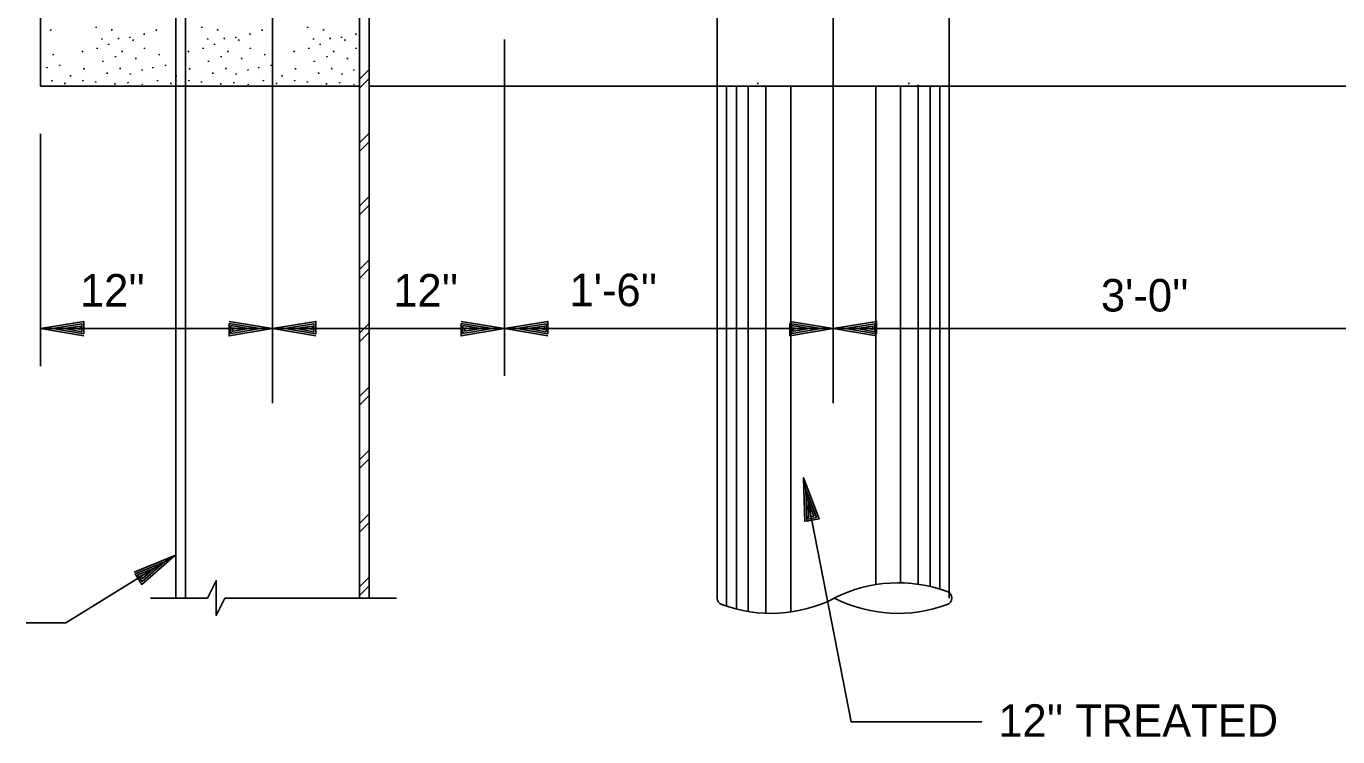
# Model space of a CAD drawing. Extents: x 0 to 320, y -4 to 473.
# Drawn here: x 7.78 to 13.43, y 11.03 to 14.09 of the extents above; entities that cross this region are included whole.
import ezdxf

# ---------------------------------------------------------------- set-up
doc = ezdxf.new("R2010")
doc.units = 0
for name, color, linetype in [('Level 1', 7, 'Continuous'), ('Level 10', 7, 'Continuous'), ('Level 2', 7, 'Continuous'), ('Level 3', 7, 'Continuous'), ('Level 50', 7, 'Continuous')]:
    doc.layers.add(name, color=color, linetype=linetype)

msp = doc.modelspace()

# ---------------------------------------------------------------- linework, layer by layer
at = {"layer": 'Level 1'}
msp.add_lwpolyline([(8.5646, 11.6278), (8.6019, 11.7028), (8.6019, 11.553), (8.6394, 11.6278)], dxfattribs=at)
at = {"layer": 'Level 10'}
for p, q in [((7.8876, 14.0729), (7.8886, 14.0789)), ((8.0843, 14.0851), (8.0839, 14.0902)), ((8.1522, 14.0748), (8.1518, 14.0799)), ((8.3436, 14.0729), (8.3445, 14.0789)), ((8.5402, 14.0851), (8.5398, 14.0902)), ((8.6081, 14.0748), (8.6077, 14.0799)), ((8.7995, 14.0729), (8.8004, 14.0789)), ((8.9962, 14.0851), (8.9957, 14.0902)), ((9.0641, 14.0748), (9.0637, 14.0799)), ((8.109, 14.0348), (8.1094, 14.0394)), ((8.1386, 14.0119), (8.1381, 14.017)), ((8.1811, 14.0374), (8.1806, 14.0426)), ((8.2303, 14.0426), (8.2299, 14.0477)), ((8.242, 14.0296), (8.2451, 14.0348)), ((8.2915, 14.0562), (8.2911, 14.0613)), ((8.5649, 14.0348), (8.5653, 14.0394)), ((8.5945, 14.0119), (8.5941, 14.017)), ((8.637, 14.0374), (8.6366, 14.0426)), ((8.6863, 14.0426), (8.6858, 14.0477)), ((8.6979, 14.0296), (8.7011, 14.0348)), ((8.7474, 14.0562), (8.747, 14.0613)), ((9.0208, 14.0348), (9.0213, 14.0394)), ((9.0504, 14.0119), (9.05, 14.017)), ((9.0929, 14.0374), (9.0925, 14.0426)), ((9.1422, 14.0426), (9.1418, 14.0477)), ((9.1539, 14.0296), (9.157, 14.0348)), ((9.2033, 14.0562), (9.2029, 14.0613)), ((7.9001, 13.9678), (7.8997, 13.9729)), ((8.0274, 13.9809), (8.0246, 13.9864)), ((8.0894, 13.9949), (8.089, 14.0001)), ((8.1675, 13.9592), (8.1671, 13.9643)), ((8.1964, 13.9813), (8.1959, 13.9864)), ((8.2931, 13.9949), (8.2927, 14.0001)), ((8.3561, 13.9678), (8.3556, 13.9729)), ((8.4833, 13.9809), (8.4805, 13.9864)), ((8.5453, 13.9949), (8.5449, 14.0001)), ((8.6234, 13.9592), (8.623, 13.9643)), ((8.6523, 13.9813), (8.6519, 13.9864)), ((8.7491, 13.9949), (8.7487, 14.0001)), ((8.812, 13.9678), (8.8116, 13.9729)), ((8.9393, 13.9809), (8.9365, 13.9864)), ((9.0013, 13.9949), (9.0008, 14.0001)), ((9.0794, 13.9592), (9.079, 13.9643)), ((9.1082, 13.9813), (9.1078, 13.9864)), ((9.205, 13.9949), (9.2046, 14.0001)), ((7.8729, 13.9117), (7.8725, 13.9168)), ((7.9273, 13.9218), (7.9269, 13.9269)), ((8.0316, 13.9066), (8.0312, 13.9117)), ((8.1131, 13.9388), (8.1127, 13.9439)), ((8.1878, 13.9083), (8.1874, 13.9134)), ((8.2558, 13.9508), (8.2554, 13.9559)), ((8.283, 13.9015), (8.2826, 13.9066)), ((8.3289, 13.9117), (8.3284, 13.9168)), ((8.3832, 13.9218), (8.3828, 13.9269)), ((8.4875, 13.9066), (8.4871, 13.9117)), ((8.5691, 13.9388), (8.5687, 13.9439)), ((8.6438, 13.9083), (8.6433, 13.9134)), ((8.7118, 13.9508), (8.7114, 13.9559)), ((8.739, 13.9015), (8.7386, 13.9066)), ((8.7848, 13.9117), (8.7844, 13.9168)), ((8.8392, 13.9218), (8.8388, 13.9269)), ((8.9434, 13.9066), (8.943, 13.9117)), ((9.025, 13.9388), (9.0246, 13.9439)), ((9.0997, 13.9083), (9.0993, 13.9134)), ((9.1677, 13.9508), (9.1673, 13.9559)), ((9.1949, 13.9015), (9.1945, 13.9066)), ((7.8933, 13.8556), (7.8929, 13.8607)), ((7.9501, 13.8424), (7.9501, 13.8487)), ((7.9739, 13.876), (7.9734, 13.8811)), ((8.0281, 13.8556), (8.0277, 13.8607)), ((8.0819, 13.8498), (8.0827, 13.8545)), ((8.1318, 13.8879), (8.1314, 13.893)), ((8.1657, 13.842), (8.1653, 13.8471)), ((8.2219, 13.8471), (8.2215, 13.8522)), ((8.232, 13.8845), (8.2316, 13.8896)), ((8.3493, 13.8556), (8.3489, 13.8607)), ((8.4061, 13.8424), (8.4061, 13.8487)), ((8.4298, 13.876), (8.4294, 13.8811)), ((8.4841, 13.8556), (8.4837, 13.8607)), ((8.5378, 13.8498), (8.5387, 13.8545)), ((8.5877, 13.8879), (8.5873, 13.893)), ((8.6217, 13.842), (8.6213, 13.8471)), ((8.6778, 13.8471), (8.6774, 13.8522)), ((8.6879, 13.8845), (8.6875, 13.8896)), ((8.8052, 13.8556), (8.8048, 13.8607)), ((8.862, 13.8424), (8.862, 13.8487)), ((8.8857, 13.876), (8.8853, 13.8811)), ((8.94, 13.8556), (8.9396, 13.8607)), ((8.9938, 13.8498), (8.9946, 13.8545)), ((9.0437, 13.8879), (9.0432, 13.893)), ((9.0776, 13.842), (9.0772, 13.8471)), ((9.1338, 13.8471), (9.1333, 13.8522)), ((9.1439, 13.8845), (9.1434, 13.8896)), ((10.9356, 13.8431), (10.9352, 13.8482)), ((11.586, 13.8431), (11.5865, 13.8482)), ((8.284, 13.8403), (8.283, 13.8437)), ((8.7399, 13.8403), (8.739, 13.8437)), ((9.1959, 13.8403), (9.1949, 13.8437)), ((10.8859, 13.8429), (10.8859, 13.8431)), ((11.6357, 13.8429), (11.6357, 13.8431))]:
    msp.add_line(p, q, dxfattribs=at)
at = {"layer": 'Level 2'}
for p, q in [((7.8442, 13.834), (7.8442, 22.584)), ((8.4275, 17.6673), (8.4275, 13.834)), ((8.4691, 11.6278), (8.4691, 17.6673)), ((9.2191, 11.6278), (9.2191, 17.6673)), ((9.2608, 11.6278), (9.2608, 17.6673)), ((11.2608, 12.4674), (11.2608, 14.9095)), ((10.7608, 14.6673), (10.7608, 13.834)), ((11.7608, 14.6673), (11.7608, 13.834)), ((9.2191, 13.8641), (9.2608, 13.9057)), ((9.2191, 13.8264), (9.2608, 13.868)), ((9.2191, 13.834), (7.8442, 13.834)), ((8.4275, 11.6278), (8.4275, 13.834)), ((15.7608, 13.834), (9.2608, 13.834)), ((10.7608, 11.6278), (10.7608, 13.834)), ((10.8014, 11.5925), (10.8014, 13.834)), ((10.8436, 11.5803), (10.8436, 13.834)), ((10.8948, 11.5698), (10.8948, 13.834)), ((10.9705, 11.5625), (10.9705, 13.834)), ((11.078, 11.5682), (11.078, 13.834)), ((11.4436, 11.686), (11.4436, 13.834)), ((11.5511, 11.6936), (11.5511, 13.834)), ((11.6269, 11.6876), (11.6269, 13.8403)), ((11.678, 11.6781), (11.678, 13.834)), ((11.7203, 11.6668), (11.7203, 13.834)), ((11.7608, 11.6278), (11.7608, 13.834)), ((9.2191, 13.5906), (9.2608, 13.6323)), ((9.2191, 13.5529), (9.2608, 13.5946)), ((9.2191, 13.3172), (9.2608, 13.3589)), ((9.2191, 13.2795), (9.2608, 13.3212)), ((9.2191, 13.0438), (9.2608, 13.0855)), ((9.2191, 13.0061), (9.2608, 13.0478)), ((9.2191, 12.7704), (9.2608, 12.8121)), ((9.2191, 12.7327), (9.2608, 12.7744)), ((9.2191, 12.497), (9.2608, 12.5386)), ((9.2191, 12.4593), (9.2608, 12.5009)), ((9.2191, 12.2236), (9.2608, 12.2652)), ((9.2191, 12.1859), (9.2608, 12.2275)), ((9.2191, 11.9501), (9.2608, 11.9918)), ((9.2191, 11.9124), (9.2608, 11.9541)), ((9.2191, 11.6768), (9.2608, 11.7184)), ((9.2191, 11.639), (9.2608, 11.6807)), ((8.5646, 11.6278), (8.3192, 11.6278)), ((8.6394, 11.6278), (9.3787, 11.6278))]:
    msp.add_line(p, q, dxfattribs=at)
for centre, radius, start, end in [((11.5406, 11.0812), 0.6125, 69.8064, 116.6071), ((11.7417, 11.6279), 0.03, 290.1936, 69.8064), ((10.7909, 11.6279), 0.03, 180, 249.6845), ((10.992, 12.1746), 0.6125, 249.8081, 296.6071), ((11.5406, 12.1746), 0.6125, 243.3929, 290.1936)]:
    msp.add_arc(centre, radius, start, end, dxfattribs=at)
at = {"layer": 'Level 3'}
for p, q in [((8.8441, 12.4674), (8.8441, 18.979)), ((9.8442, 12.5854), (9.8442, 14.0361)), ((7.8442, 12.6273), (7.8442, 13.6296)), ((8.8441, 12.7892), (7.8442, 12.7892)), ((8.8441, 12.7892), (9.8442, 12.7892)), ((9.8442, 12.7892), (11.2608, 12.7892)), ((14.2608, 12.7892), (11.2608, 12.7892))]:
    msp.add_line(p, q, dxfattribs=at)
for points in [[(11.9015, 11.0948), (11.3378, 11.0948), (11.1332, 12.1467)], [(7.7831, 11.5219), (7.954, 11.5219), (8.4239, 11.8115)]]:
    msp.add_lwpolyline(points, dxfattribs=at)
at = {"layer": 'Level 50'}
for p, q in [((7.8442, 12.7892), (7.8442, 12.7892)), ((7.8962, 12.7892), (7.8962, 12.7892)), ((8.7921, 12.7892), (8.7921, 12.7892)), ((8.8441, 12.7892), (8.8441, 12.7892)), ((8.8441, 12.7892), (8.8441, 12.7892)), ((8.8961, 12.7892), (8.8961, 12.7892)), ((9.7922, 12.7892), (9.7922, 12.7892)), ((9.8442, 12.7892), (9.8442, 12.7892)), ((9.8442, 12.7892), (9.8442, 12.7892)), ((9.8962, 12.7892), (9.8962, 12.7892)), ((11.2088, 12.7892), (11.2088, 12.7892)), ((11.2608, 12.7892), (11.2608, 12.7892)), ((11.2608, 12.7892), (11.2608, 12.7892)), ((11.3128, 12.7892), (11.3128, 12.7892)), ((11.1332, 12.1467), (11.1332, 12.1467)), ((11.1432, 12.0956), (11.1432, 12.0956)), ((8.3796, 11.7842), (8.3796, 11.7842)), ((8.4239, 11.8115), (8.4239, 11.8115))]:
    msp.add_line(p, q, dxfattribs=at)
for points in [[(8.0312, 12.7582), (7.8442, 12.7892), (8.0312, 12.8202), (8.0312, 12.7672), (7.8962, 12.7892), (8.0232, 12.8102), (8.0232, 12.7762), (7.9462, 12.7892), (8.0152, 12.8002), (8.0152, 12.7862), (7.9982, 12.7892)], [(8.6571, 12.8202), (8.8441, 12.7892), (8.6571, 12.7582), (8.6571, 12.8112), (8.7921, 12.7892), (8.6651, 12.7682), (8.6651, 12.8022), (8.7421, 12.7892), (8.6731, 12.7782), (8.6731, 12.7922), (8.6901, 12.7892)], [(9.0311, 12.7582), (8.8441, 12.7892), (9.0311, 12.8202), (9.0311, 12.7672), (8.8961, 12.7892), (9.0231, 12.8102), (9.0231, 12.7762), (8.9461, 12.7892), (9.0151, 12.8002), (9.0151, 12.7862), (8.9981, 12.7892)], [(9.6572, 12.8202), (9.8442, 12.7892), (9.6572, 12.7582), (9.6572, 12.8112), (9.7922, 12.7892), (9.6652, 12.7682), (9.6652, 12.8022), (9.7422, 12.7892), (9.6732, 12.7782), (9.6732, 12.7922), (9.6902, 12.7892)], [(10.0312, 12.7582), (9.8442, 12.7892), (10.0312, 12.8202), (10.0312, 12.7672), (9.8962, 12.7892), (10.0232, 12.8102), (10.0232, 12.7762), (9.9462, 12.7892), (10.0152, 12.8002), (10.0152, 12.7862), (9.9982, 12.7892)], [(11.0738, 12.8202), (11.2608, 12.7892), (11.0738, 12.7582), (11.0738, 12.8112), (11.2088, 12.7892), (11.0818, 12.7682), (11.0818, 12.8022), (11.1588, 12.7892), (11.0898, 12.7782), (11.0898, 12.7922), (11.1068, 12.7892)], [(11.4478, 12.7582), (11.2608, 12.7892), (11.4478, 12.8202), (11.4478, 12.7672), (11.3128, 12.7892), (11.4398, 12.8102), (11.4398, 12.7762), (11.3628, 12.7892), (11.4318, 12.8002), (11.4318, 12.7862), (11.4148, 12.7892)], [(11.1385, 11.9572), (11.1332, 12.1467), (11.1994, 11.969), (11.1473, 11.9589), (11.1432, 12.0956), (11.188, 11.975), (11.1546, 11.9685), (11.1527, 12.0466), (11.1767, 11.9809), (11.1629, 11.9783), (11.1626, 11.9955)], [(8.2484, 11.7398), (8.4239, 11.8115), (8.281, 11.687), (8.2532, 11.7321), (8.3796, 11.7842), (8.2825, 11.6997), (8.2647, 11.7287), (8.3371, 11.758), (8.2841, 11.7124), (8.2768, 11.7243), (8.2928, 11.7307)]]:
    msp.add_lwpolyline(points, dxfattribs=at)

# ---------------------------------------------------------------- texts
at = {"layer": 'Level 3'}
for s, p in [("12''", (8.0148, 12.8846)), ("12''", (9.365, 12.8846)), ("1'-6''", (10.1243, 12.8861)), ("3'-0''", (12.4143, 12.8631)), ("12'' TREATED ", (11.9722, 11.0302))]:
    msp.add_text(s, height=0.14, dxfattribs=at).set_placement(p)

doc.saveas('drawing.dxf')
